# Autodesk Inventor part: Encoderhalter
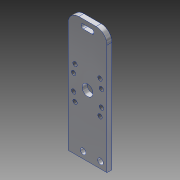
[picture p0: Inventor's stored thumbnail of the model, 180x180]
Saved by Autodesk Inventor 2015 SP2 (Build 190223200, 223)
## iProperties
Created: 2012-07
Part Number: Encoderhalter
Material: Aluminium 6061
Document SubType Name: Modeling
Designer: rYan
Density: 2.71 g/cm^3
Mass: 5.48738 g
Surface Area: 21.937 cm^2
Volume: 2.02486 cm^3
Appearance: Aluminium - flach
Author: rYan
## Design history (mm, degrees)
sketch "Skizze5"
  geometry: L1 (0, -11.2)-(0, 67.2) reference; L2 (-9, 0)-(9, 0); L3 (9, 56)-(-9, 56); L4 (12.6, 0)-(-12.6, 0) reference; L5 (9, 0)-(9, 56); L6 (9, 56)-(-9, 56); L7 (-9, 56)-(-9, 0); 1 further point
  constraints: 10 end point, 2 parallel, 1 collinear, 1 horizontal, 1 symmetric about line, 1 other
  dimensions: "d89" = 18 distance of L3.start L3.end; "d91" = 56 distance between parallel lines of L4 L3
extrude "Extrusion2" new body sketch "Skizze5" distance "d51" = 2.3; taper "d52" = 0 deg
sketch "Skizze6"
  geometry: L1 (0, 67.2)-(0, -11.2) reference; L2 (-12.6, 0)-(12.6, 0) reference; 2 further points
  constraints: 1 point on line
  dimensions: "d92" = 28.5 distance from line of L2 point (0, 28.5)
hole "Bohrung4" sketch "Skizze6" at (0, 28.5) diameter "d53" = 5; stored, may be unused: countersink angle "d57" = 90 deg, drill point angle "d59" = 118 deg; dims "d54" = 6, "d55" = 4, "d56" = 2, "d58" = 8
sketch "Skizze7"
  geometry: L1 (0, 28.5)-(5.772, 36.077); L2 (0, 67.2)-(0, -11.2) reference; L3 (0, 28.5)-(-5.772, 36.077); C1 r 2.5 at (0, 28.5) reference; A1 r 9.525 centre (0, 28.5) between (5.772, 36.077) and (-5.772, 36.077); 2 further points
  constraints: 4 end point, 2 coincident, 2 point on circle, 1 centre point
  dimensions: "d60" = 19.05 diameter of A1; "d61" = 37.3 deg angle of L1 L2; "d110" = 37.3 deg angle of L3 L2 (= d61)
hole "Bohrung5" sketch "Skizze7" at (5.772, 36.077), (-5.772, 36.077) diameter "d63" = 2.013; stored, may be unused: countersink angle "d67" = 90 deg, drill point angle "d69" = 118 deg; dims "d64" = 6, "d65" = 4, "d66" = 2, "d68" = 8
sketch "Skizze11"
  geometry: L1 (0, 28.5)-(-6.443, 32.22); L2 (0, 67.2)-(0, -11.2) reference; L3 (0, 28.5)-(6.443, 32.22); C1 r 2.5 at (0, 28.5) reference; A1 r 7.44 centre (0, 28.5) between (-6.443, 32.22) and (6.443, 32.22); 3 further points
  constraints: 4 end point, 3 coincident, 2 point on circle, 1 centre point, 1 symmetric about line
  dimensions: "d116" = 14.88 diameter of A1; "d117" = 60 deg angle of L2 L1
hole "Bohrung7" sketch "Skizze11" at (-6.443, 32.22), (6.443, 32.22) diameter "d118" = 2.013; stored, may be unused: countersink angle "d122" = 90 deg, drill point angle "d124" = 118 deg; dims "d119" = 5, "d120" = 4, "d121" = 2, "d123" = 7.6
pattern_circular "Runde Anordnung2" dims angle "d71" = 360 deg
fillet "Rundung5" dims "d100" = 5
sketch "Skizze8"
  geometry: L1 (0, 67.2)-(0, -11.202) reference; L2 (-2, 3)-(6, 3); L3 (-24, 0)-(14.5, 0) reference; L4 (9, 0)-(-9, 0) reference; 2 further points
  constraints: 2 end point, 1 parallel
  dimensions: "d106" = 8 distance of L2.end L2.start; "d108" = 3 distance between parallel lines of L3 L2; "d109" = 2 distance from line of L2.start L1
hole "Bohrung6" sketch "Skizze8" diameter "d73" = 2.6; stored, may be unused: countersink angle "d77" = 90 deg, drill point angle "d79" = 118 deg; dims "d74" = 6, "d75" = 4, "d76" = 2, "d78" = 8
sketch "Skizze10"
  geometry: L1 (-2, 53)-(2, 53); L2 (-2, 52)-(2, 52); L3 (2, 54)-(-2, 54); L4 (-9, 56)-(9, 56) reference; L5 (0, 69.6)-(0, -11.6) reference; A1 r 1 centre (-2, 53) between (-2, 54) and (-2, 52); A2 r 1 centre (2, 53) between (2, 52) and (2, 54); 4 further points
  constraints: 8 end point, 4 point on circle, 4 tangent, 2 centre point, 1 horizontal, 1 midpoint, 1 parallel, 1 point on line
  dimensions: "d111" = 4 distance of L1.start L1.end; "d112" = 1 radius of A2; "d113" = 2 distance between parallel lines of L4 L3
extrude "Extrusion4" cut sketch "Skizze10" stored distance "d114" = 10; taper "d115" = 0 deg
node "Volumenkörper1"
other parameters: "d43" = 28
